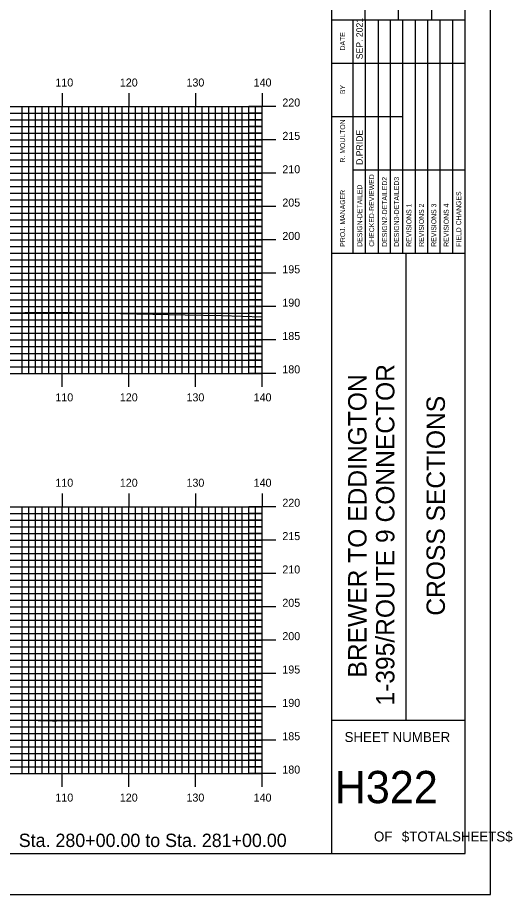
# Model space of a CAD drawing. Extents: x 1810980 to 1811323, y 442591 to 442811.
# Drawn here: x 1811249.2 to 1811323.4, y 442590.5 to 442722 of the extents above; entities that cross this region are included whole.
import ezdxf

# ---------------------------------------------------------------- set-up
doc = ezdxf.new("R2010")
doc.units = 0
for name, color, linetype in [('BORDER', 7, 'Continuous'), ('H_V ANNOTATION', 7, 'Continuous'), ('MAJOR', 7, 'Continuous'), ('MINOR', 7, 'Continuous'), ('PLOT BOUNDARY', 7, 'Continuous'), ('S_Roadway_Centerline', 7, 'Continuous')]:
    doc.layers.add(name, color=color, linetype=linetype)

msp = doc.modelspace()

# ---------------------------------------------------------------- linework, layer by layer
at = {"layer": 'BORDER'}
for p, q in [((1811296.29, 442596.67), (1811296.29, 442806.67)), ((1811301.29, 442721.67), (1811301.29, 442738.97)), ((1811306.29, 442721.67), (1811306.29, 442738.97)), ((1811311.29, 442721.67), (1811311.29, 442738.97)), ((1811296.29, 442721.67), (1811316.29, 442721.67)), ((1811296.29, 442686.67), (1811316.29, 442686.67)), ((1811307.47, 442616.67), (1811307.47, 442686.67)), ((1811296.29, 442616.67), (1811316.29, 442616.67))]:
    msp.add_line(p, q, dxfattribs=at)
msp.add_lwpolyline([(1810996.29, 442596.67), (1811316.29, 442596.67), (1811316.29, 442806.67), (1810996.29, 442806.67)], close=True, dxfattribs=at)
for points in [[(1811299.52, 442715.17), (1811299.52, 442721.67)], [(1811301.38, 442686.68), (1811301.38, 442721.67)], [(1811303.25, 442721.67), (1811303.25, 442686.68)], [(1811305.11, 442686.68), (1811305.11, 442721.67)], [(1811306.97, 442686.68), (1811306.97, 442721.67)], [(1811308.84, 442686.68), (1811308.84, 442721.67)], [(1811310.7, 442686.68), (1811310.7, 442721.67)], [(1811312.56, 442686.68), (1811312.56, 442721.67)], [(1811314.43, 442686.68), (1811314.43, 442721.67)], [(1811299.52, 442686.68), (1811299.52, 442720.26)], [(1811296.29, 442715.17), (1811316.29, 442715.17)], [(1811296.29, 442707.17), (1811299.52, 442707.17)], [(1811299.52, 442707.17), (1811306.97, 442707.17)], [(1811299.52, 442699.17), (1811316.29, 442699.17)]]:
    msp.add_lwpolyline(points, dxfattribs=at)
at = {"layer": 'MAJOR'}
for p, q in [((1811255.89, 442710.67), (1811255.89, 442708.67)), ((1811265.89, 442710.67), (1811265.89, 442708.67)), ((1811275.89, 442710.67), (1811275.89, 442708.67)), ((1811285.89, 442710.67), (1811285.89, 442708.67)), ((1811005.89, 442708.67), (1811285.89, 442708.67)), ((1811005.89, 442708.67), (1811285.89, 442708.67)), ((1811255.89, 442668.67), (1811255.89, 442708.67)), ((1811265.89, 442668.67), (1811265.89, 442708.67)), ((1811275.89, 442668.67), (1811275.89, 442708.67)), ((1811287.89, 442708.67), (1811283.89, 442708.67)), ((1811285.89, 442668.67), (1811285.89, 442708.67)), ((1811285.89, 442668.67), (1811285.89, 442708.67)), ((1811005.89, 442703.67), (1811285.89, 442703.67)), ((1811287.89, 442703.67), (1811283.89, 442703.67)), ((1811005.89, 442698.67), (1811285.89, 442698.67)), ((1811287.89, 442698.67), (1811283.89, 442698.67)), ((1811005.89, 442693.67), (1811285.89, 442693.67)), ((1811287.89, 442693.67), (1811283.89, 442693.67)), ((1811005.89, 442688.67), (1811285.89, 442688.67)), ((1811287.89, 442688.67), (1811283.89, 442688.67)), ((1811005.89, 442683.67), (1811285.89, 442683.67)), ((1811287.89, 442683.67), (1811283.89, 442683.67)), ((1811005.89, 442678.67), (1811285.89, 442678.67)), ((1811287.89, 442678.67), (1811283.89, 442678.67)), ((1811005.89, 442673.67), (1811285.89, 442673.67)), ((1811287.89, 442673.67), (1811283.89, 442673.67)), ((1811005.89, 442668.67), (1811285.89, 442668.67)), ((1811005.89, 442668.67), (1811285.89, 442668.67)), ((1811255.89, 442666.66), (1811255.89, 442668.67)), ((1811265.89, 442666.66), (1811265.89, 442668.67)), ((1811275.89, 442666.66), (1811275.89, 442668.67)), ((1811287.89, 442668.67), (1811283.89, 442668.67)), ((1811285.89, 442666.66), (1811285.89, 442668.67)), ((1811255.89, 442650.67), (1811255.89, 442648.67)), ((1811265.89, 442650.67), (1811265.89, 442648.67)), ((1811275.89, 442650.67), (1811275.89, 442648.67)), ((1811285.89, 442650.67), (1811285.89, 442648.67)), ((1811005.89, 442648.67), (1811285.89, 442648.67)), ((1811005.89, 442648.67), (1811285.89, 442648.67)), ((1811255.89, 442608.67), (1811255.89, 442648.67)), ((1811265.89, 442608.67), (1811265.89, 442648.67)), ((1811275.89, 442608.67), (1811275.89, 442648.67)), ((1811287.89, 442648.67), (1811283.89, 442648.67)), ((1811285.89, 442608.67), (1811285.89, 442648.67)), ((1811285.89, 442608.67), (1811285.89, 442648.67)), ((1811005.89, 442643.67), (1811285.89, 442643.67)), ((1811287.89, 442643.67), (1811283.89, 442643.67)), ((1811005.89, 442638.67), (1811285.89, 442638.67)), ((1811287.89, 442638.67), (1811283.89, 442638.67)), ((1811005.89, 442633.67), (1811285.89, 442633.67)), ((1811287.89, 442633.67), (1811283.89, 442633.67)), ((1811005.89, 442628.67), (1811285.89, 442628.67)), ((1811287.89, 442628.67), (1811283.89, 442628.67)), ((1811005.89, 442623.67), (1811285.89, 442623.67)), ((1811287.89, 442623.67), (1811283.89, 442623.67)), ((1811005.89, 442618.67), (1811285.89, 442618.67)), ((1811287.89, 442618.67), (1811283.89, 442618.67)), ((1811005.89, 442613.67), (1811285.89, 442613.67)), ((1811287.89, 442613.67), (1811283.89, 442613.67)), ((1811005.89, 442608.67), (1811285.89, 442608.67)), ((1811005.89, 442608.67), (1811285.89, 442608.67)), ((1811255.89, 442606.66), (1811255.89, 442608.67)), ((1811265.89, 442606.66), (1811265.89, 442608.67)), ((1811275.89, 442606.66), (1811275.89, 442608.67)), ((1811287.89, 442608.67), (1811283.89, 442608.67)), ((1811285.89, 442606.66), (1811285.89, 442608.67))]:
    msp.add_line(p, q, dxfattribs=at)
at = {"layer": 'MINOR'}
for p, q in [((1811249.89, 442668.67), (1811249.89, 442708.67)), ((1811250.89, 442668.67), (1811250.89, 442708.67)), ((1811251.89, 442668.67), (1811251.89, 442708.67)), ((1811252.89, 442668.67), (1811252.89, 442708.67)), ((1811253.89, 442668.67), (1811253.89, 442708.67)), ((1811254.89, 442668.67), (1811254.89, 442708.67)), ((1811256.89, 442668.67), (1811256.89, 442708.67)), ((1811257.89, 442668.67), (1811257.89, 442708.67)), ((1811258.89, 442668.67), (1811258.89, 442708.67)), ((1811259.89, 442668.67), (1811259.89, 442708.67)), ((1811260.89, 442668.67), (1811260.89, 442708.67)), ((1811261.89, 442668.67), (1811261.89, 442708.67)), ((1811262.89, 442668.67), (1811262.89, 442708.67)), ((1811263.89, 442668.67), (1811263.89, 442708.67)), ((1811264.89, 442668.67), (1811264.89, 442708.67)), ((1811266.89, 442668.67), (1811266.89, 442708.67)), ((1811267.89, 442668.67), (1811267.89, 442708.67)), ((1811268.89, 442668.67), (1811268.89, 442708.67)), ((1811269.89, 442668.67), (1811269.89, 442708.67)), ((1811270.89, 442668.67), (1811270.89, 442708.67)), ((1811271.89, 442668.67), (1811271.89, 442708.67)), ((1811272.89, 442668.67), (1811272.89, 442708.67)), ((1811273.89, 442668.67), (1811273.89, 442708.67)), ((1811274.89, 442668.67), (1811274.89, 442708.67)), ((1811276.89, 442668.67), (1811276.89, 442708.67)), ((1811277.89, 442668.67), (1811277.89, 442708.67)), ((1811278.89, 442668.67), (1811278.89, 442708.67)), ((1811279.89, 442668.67), (1811279.89, 442708.67)), ((1811280.89, 442668.67), (1811280.89, 442708.67)), ((1811281.89, 442668.67), (1811281.89, 442708.67)), ((1811282.89, 442668.67), (1811282.89, 442708.67)), ((1811283.89, 442668.67), (1811283.89, 442708.67)), ((1811284.89, 442668.67), (1811284.89, 442708.67)), ((1811005.89, 442707.67), (1811285.89, 442707.67)), ((1811285.89, 442707.67), (1811283.89, 442707.67)), ((1811005.89, 442706.67), (1811285.89, 442706.67)), ((1811005.89, 442705.67), (1811285.89, 442705.67)), ((1811285.89, 442706.67), (1811283.89, 442706.67)), ((1811285.89, 442705.67), (1811283.89, 442705.67)), ((1811005.89, 442704.67), (1811285.89, 442704.67)), ((1811285.89, 442704.67), (1811283.89, 442704.67)), ((1811005.89, 442702.67), (1811285.89, 442702.67)), ((1811005.89, 442701.67), (1811285.89, 442701.67)), ((1811285.89, 442702.67), (1811283.89, 442702.67)), ((1811285.89, 442701.67), (1811283.89, 442701.67)), ((1811005.89, 442700.67), (1811285.89, 442700.67)), ((1811285.89, 442700.67), (1811283.89, 442700.67)), ((1811005.89, 442699.67), (1811285.89, 442699.67)), ((1811285.89, 442699.67), (1811283.89, 442699.67)), ((1811005.89, 442697.67), (1811285.89, 442697.67)), ((1811285.89, 442697.67), (1811283.89, 442697.67)), ((1811005.89, 442696.67), (1811285.89, 442696.67)), ((1811285.89, 442696.67), (1811283.89, 442696.67)), ((1811005.89, 442695.67), (1811285.89, 442695.67)), ((1811285.89, 442695.67), (1811283.89, 442695.67)), ((1811005.89, 442694.67), (1811285.89, 442694.67)), ((1811285.89, 442694.67), (1811283.89, 442694.67)), ((1811005.89, 442692.67), (1811285.89, 442692.67)), ((1811285.89, 442692.67), (1811283.89, 442692.67)), ((1811005.89, 442691.67), (1811285.89, 442691.67)), ((1811285.89, 442691.67), (1811283.89, 442691.67)), ((1811005.89, 442690.67), (1811285.89, 442690.67)), ((1811285.89, 442690.67), (1811283.89, 442690.67)), ((1811005.89, 442689.67), (1811285.89, 442689.67)), ((1811285.89, 442689.67), (1811283.89, 442689.67)), ((1811005.89, 442687.67), (1811285.89, 442687.67)), ((1811285.89, 442687.67), (1811283.89, 442687.67)), ((1811005.89, 442686.67), (1811285.89, 442686.67)), ((1811285.89, 442686.67), (1811283.89, 442686.67)), ((1811005.89, 442685.67), (1811285.89, 442685.67)), ((1811005.89, 442684.67), (1811285.89, 442684.67)), ((1811285.89, 442685.67), (1811283.89, 442685.67)), ((1811285.89, 442684.67), (1811283.89, 442684.67)), ((1811005.89, 442682.67), (1811285.89, 442682.67)), ((1811285.89, 442682.67), (1811283.89, 442682.67)), ((1811005.89, 442681.67), (1811285.89, 442681.67)), ((1811005.89, 442680.67), (1811285.89, 442680.67)), ((1811285.89, 442681.67), (1811283.89, 442681.67)), ((1811285.89, 442680.67), (1811283.89, 442680.67)), ((1811005.89, 442679.67), (1811285.89, 442679.67)), ((1811285.89, 442679.67), (1811283.89, 442679.67)), ((1811005.89, 442677.67), (1811285.89, 442677.67)), ((1811005.89, 442676.67), (1811285.89, 442676.67)), ((1811285.89, 442677.67), (1811283.89, 442677.67)), ((1811285.89, 442676.67), (1811283.89, 442676.67)), ((1811005.89, 442675.67), (1811285.89, 442675.67)), ((1811285.89, 442675.67), (1811283.89, 442675.67)), ((1811005.89, 442674.67), (1811285.89, 442674.67)), ((1811285.89, 442674.67), (1811283.89, 442674.67)), ((1811005.89, 442672.67), (1811285.89, 442672.67)), ((1811285.89, 442672.67), (1811283.89, 442672.67)), ((1811005.89, 442671.67), (1811285.89, 442671.67)), ((1811285.89, 442671.67), (1811283.89, 442671.67)), ((1811005.89, 442670.67), (1811285.89, 442670.67)), ((1811285.89, 442670.67), (1811283.89, 442670.67)), ((1811005.89, 442669.67), (1811285.89, 442669.67)), ((1811285.89, 442669.67), (1811283.89, 442669.67)), ((1811005.89, 442647.67), (1811285.89, 442647.67)), ((1811249.89, 442608.67), (1811249.89, 442648.67)), ((1811250.89, 442608.67), (1811250.89, 442648.67)), ((1811251.89, 442608.67), (1811251.89, 442648.67)), ((1811252.89, 442608.67), (1811252.89, 442648.67)), ((1811253.89, 442608.67), (1811253.89, 442648.67)), ((1811254.89, 442608.67), (1811254.89, 442648.67)), ((1811256.89, 442608.67), (1811256.89, 442648.67)), ((1811257.89, 442608.67), (1811257.89, 442648.67)), ((1811258.89, 442608.67), (1811258.89, 442648.67)), ((1811259.89, 442608.67), (1811259.89, 442648.67)), ((1811260.89, 442608.67), (1811260.89, 442648.67)), ((1811261.89, 442608.67), (1811261.89, 442648.67)), ((1811262.89, 442608.67), (1811262.89, 442648.67)), ((1811263.89, 442608.67), (1811263.89, 442648.67)), ((1811264.89, 442608.67), (1811264.89, 442648.67)), ((1811266.89, 442608.67), (1811266.89, 442648.67)), ((1811267.89, 442608.67), (1811267.89, 442648.67)), ((1811268.89, 442608.67), (1811268.89, 442648.67)), ((1811269.89, 442608.67), (1811269.89, 442648.67)), ((1811270.89, 442608.67), (1811270.89, 442648.67)), ((1811271.89, 442608.67), (1811271.89, 442648.67)), ((1811272.89, 442608.67), (1811272.89, 442648.67)), ((1811273.89, 442608.67), (1811273.89, 442648.67)), ((1811274.89, 442608.67), (1811274.89, 442648.67)), ((1811276.89, 442608.67), (1811276.89, 442648.67)), ((1811277.89, 442608.67), (1811277.89, 442648.67)), ((1811278.89, 442608.67), (1811278.89, 442648.67)), ((1811279.89, 442608.67), (1811279.89, 442648.67)), ((1811280.89, 442608.67), (1811280.89, 442648.67)), ((1811281.89, 442608.67), (1811281.89, 442648.67)), ((1811282.89, 442608.67), (1811282.89, 442648.67)), ((1811283.89, 442608.67), (1811283.89, 442648.67)), ((1811285.89, 442647.67), (1811283.89, 442647.67)), ((1811284.89, 442608.67), (1811284.89, 442648.67)), ((1811005.89, 442646.67), (1811285.89, 442646.67)), ((1811285.89, 442646.67), (1811283.89, 442646.67)), ((1811005.89, 442645.67), (1811285.89, 442645.67)), ((1811285.89, 442645.67), (1811283.89, 442645.67)), ((1811005.89, 442644.67), (1811285.89, 442644.67)), ((1811285.89, 442644.67), (1811283.89, 442644.67)), ((1811005.89, 442642.67), (1811285.89, 442642.67)), ((1811285.89, 442642.67), (1811283.89, 442642.67)), ((1811005.89, 442641.67), (1811285.89, 442641.67)), ((1811285.89, 442641.67), (1811283.89, 442641.67)), ((1811005.89, 442640.67), (1811285.89, 442640.67)), ((1811285.89, 442640.67), (1811283.89, 442640.67)), ((1811005.89, 442639.67), (1811285.89, 442639.67)), ((1811285.89, 442639.67), (1811283.89, 442639.67)), ((1811005.89, 442637.67), (1811285.89, 442637.67)), ((1811285.89, 442637.67), (1811283.89, 442637.67)), ((1811005.89, 442636.67), (1811285.89, 442636.67)), ((1811285.89, 442636.67), (1811283.89, 442636.67)), ((1811005.89, 442635.67), (1811285.89, 442635.67)), ((1811005.89, 442634.67), (1811285.89, 442634.67)), ((1811285.89, 442635.67), (1811283.89, 442635.67)), ((1811285.89, 442634.67), (1811283.89, 442634.67)), ((1811005.89, 442632.67), (1811285.89, 442632.67)), ((1811285.89, 442632.67), (1811283.89, 442632.67)), ((1811005.89, 442631.67), (1811285.89, 442631.67)), ((1811005.89, 442630.67), (1811285.89, 442630.67)), ((1811285.89, 442631.67), (1811283.89, 442631.67)), ((1811285.89, 442630.67), (1811283.89, 442630.67)), ((1811005.89, 442629.67), (1811285.89, 442629.67)), ((1811285.89, 442629.67), (1811283.89, 442629.67)), ((1811005.89, 442627.67), (1811285.89, 442627.67)), ((1811005.89, 442626.67), (1811285.89, 442626.67)), ((1811285.89, 442627.67), (1811283.89, 442627.67)), ((1811285.89, 442626.67), (1811283.89, 442626.67)), ((1811005.89, 442625.67), (1811285.89, 442625.67)), ((1811285.89, 442625.67), (1811283.89, 442625.67)), ((1811005.89, 442624.67), (1811285.89, 442624.67)), ((1811285.89, 442624.67), (1811283.89, 442624.67)), ((1811005.89, 442622.67), (1811285.89, 442622.67)), ((1811285.89, 442622.67), (1811283.89, 442622.67)), ((1811005.89, 442621.67), (1811285.89, 442621.67)), ((1811285.89, 442621.67), (1811283.89, 442621.67)), ((1811005.89, 442620.67), (1811285.89, 442620.67)), ((1811285.89, 442620.67), (1811283.89, 442620.67)), ((1811005.89, 442619.67), (1811285.89, 442619.67)), ((1811285.89, 442619.67), (1811283.89, 442619.67)), ((1811005.89, 442617.67), (1811285.89, 442617.67)), ((1811285.89, 442617.67), (1811283.89, 442617.67)), ((1811005.89, 442616.67), (1811285.89, 442616.67)), ((1811285.89, 442616.67), (1811283.89, 442616.67)), ((1811005.89, 442615.67), (1811285.89, 442615.67)), ((1811285.89, 442615.67), (1811283.89, 442615.67)), ((1811005.89, 442614.67), (1811285.89, 442614.67)), ((1811285.89, 442614.67), (1811283.89, 442614.67)), ((1811005.89, 442612.67), (1811285.89, 442612.67)), ((1811285.89, 442612.67), (1811283.89, 442612.67)), ((1811005.89, 442611.67), (1811285.89, 442611.67)), ((1811285.89, 442611.67), (1811283.89, 442611.67)), ((1811005.89, 442610.67), (1811285.89, 442610.67)), ((1811005.89, 442609.67), (1811285.89, 442609.67)), ((1811285.89, 442610.67), (1811283.89, 442610.67)), ((1811285.89, 442609.67), (1811283.89, 442609.67))]:
    msp.add_line(p, q, dxfattribs=at)
at = {"layer": 'PLOT BOUNDARY'}
msp.add_lwpolyline([(1810980.1, 442590.55), (1811320.1, 442590.55), (1811320.1, 442810.55), (1810980.1, 442810.55)], close=True, dxfattribs=at)
at = {"layer": 'S_Roadway_Centerline'}
for points in [[(1811167.63, 442678.4), (1811180.71, 442678.13), (1811186.64, 442677.97), (1811187.66, 442677.97), (1811189.85, 442677.99), (1811200.35, 442678.35), (1811207.61, 442678.11), (1811217.8, 442677.8), (1811223.46, 442677.62), (1811227.5, 442677.57), (1811250.31, 442677.78), (1811255.91, 442677.81), (1811256.5, 442677.81), (1811257.39, 442677.79), (1811274.31, 442677.46), (1811279.78, 442677.33), (1811285.89, 442677.14)], [(1811173.27, 442618.12), (1811192.61, 442617.86), (1811196.26, 442617.76), (1811201.92, 442617.56), (1811213.61, 442617.35), (1811229.63, 442617.02), (1811233.98, 442616.96), (1811252.28, 442616.64), (1811254.46, 442616.6), (1811255.04, 442616.59), (1811274.55, 442616.79), (1811284.49, 442616.68), (1811285.89, 442616.62)]]:
    msp.add_lwpolyline(points, dxfattribs=at)

# ---------------------------------------------------------------- texts
at = {"layer": 'BORDER'}
for s, height, p in [('SEP. 2021', 0.969, (1811300.94, 442715.76)), ('DATE', 0.743, (1811298.3, 442717.08)), ('BY', 0.743, (1811298.3, 442710.54)), ('R. MOULTON', 0.745, (1811298.3, 442700.28)), ('D.PRIDE', 0.969, (1811300.94, 442699.92)), ('CHECKED-REVIEWED', 0.7455, (1811302.65, 442687.65)), ('DESIGN2-DETAILED2', 0.7455, (1811304.59, 442687.65)), ('DESIGN3-DETAILED3', 0.7455, (1811306.38, 442687.65)), ('DESIGN-DETAILED', 0.7455, (1811300.86, 442687.65)), ('PROJ. MANAGER', 0.7455, (1811298.3, 442687.65)), ('FIELD CHANGES', 0.7455, (1811315.7, 442687.65)), ('REVISIONS 1', 0.7455, (1811308.24, 442687.65)), ('REVISIONS 2', 0.7455, (1811310.11, 442687.65)), ('REVISIONS 3', 0.7455, (1811311.97, 442687.65)), ('REVISIONS 4', 0.7455, (1811313.83, 442687.65)), ('1-395/ROUTE 9 CONNECTOR', 2.7557, (1811305.69, 442618.87)), ('BREWER TO EDDINGTON', 2.7557, (1811301.51, 442623.07)), ('CROSS SECTIONS', 2.7557, (1811313.26, 442632.34))]:
    msp.add_text(s, height=height, rotation=90, dxfattribs=at).set_placement(p)
for s, height, p in [('SHEET NUMBER', 1.4905, (1811298.22, 442613.4)), ('H322', 4.839, (1811296.73, 442604.23)), ('OF', 1.491, (1811302.62, 442598.49)), ('$TOTALSHEETS$', 1.4905, (1811306.8, 442598.49))]:
    msp.add_text(s, height=height, dxfattribs=at).set_placement(p)
at = {"layer": 'H_V ANNOTATION'}
for s, height, p in [('110', 1.2, (1811254.87, 442711.67)), ('120', 1.2, (1811264.53, 442711.67)), ('130', 1.2, (1811274.52, 442711.67)), ('140', 1.2, (1811284.59, 442711.67)), ('220', 1.2, (1811288.89, 442708.67)), ('215', 1.2, (1811288.89, 442703.67)), ('210', 1.2, (1811288.89, 442698.67)), ('205', 1.2, (1811288.89, 442693.67)), ('200', 1.2, (1811288.89, 442688.67)), ('195', 1.2, (1811288.89, 442683.67)), ('190', 1.2, (1811288.89, 442678.67)), ('185', 1.2, (1811288.89, 442673.67)), ('180', 1.2, (1811288.89, 442668.67)), ('110', 1.2, (1811254.87, 442664.47)), ('120', 1.2, (1811264.53, 442664.47)), ('130', 1.2, (1811274.52, 442664.47)), ('140', 1.2, (1811284.59, 442664.47)), ('110', 1.2, (1811254.87, 442651.67)), ('120', 1.2, (1811264.53, 442651.67)), ('130', 1.2, (1811274.52, 442651.67)), ('140', 1.2, (1811284.59, 442651.67)), ('220', 1.2, (1811288.89, 442648.67)), ('215', 1.2, (1811288.89, 442643.67)), ('210', 1.2, (1811288.89, 442638.67)), ('205', 1.2, (1811288.89, 442633.67)), ('200', 1.2, (1811288.89, 442628.67)), ('195', 1.2, (1811288.89, 442623.67)), ('190', 1.2, (1811288.89, 442618.67)), ('185', 1.2, (1811288.89, 442613.67)), ('180', 1.2, (1811288.89, 442608.67)), ('110', 1.2, (1811254.87, 442604.47)), ('120', 1.2, (1811264.53, 442604.47)), ('130', 1.2, (1811274.52, 442604.47)), ('140', 1.2, (1811284.59, 442604.47)), ('Sta. 280+00.00 to Sta. 281+00.00', 2.0004, (1811249.38, 442597.66))]:
    msp.add_text(s, height=height, dxfattribs=at).set_placement(p)

doc.saveas('drawing.dxf')
